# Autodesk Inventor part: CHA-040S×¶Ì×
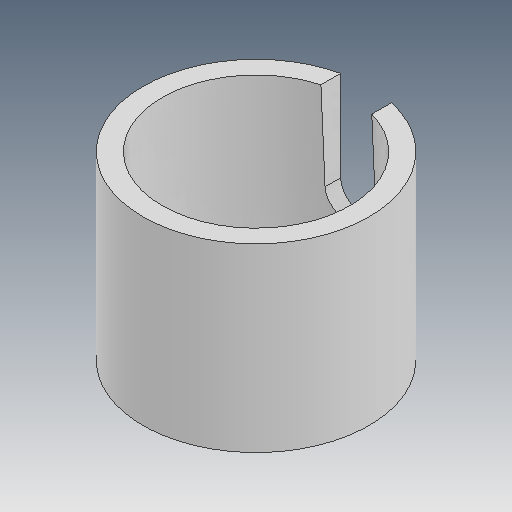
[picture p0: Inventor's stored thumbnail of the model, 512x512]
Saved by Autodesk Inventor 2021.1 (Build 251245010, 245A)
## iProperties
Created: 2019-05
Part Number: CHA-040S×¶Ì×
Material: Ogólny
Document SubType Name: Modeling
Designer: user
Density: 1 g/cm^3
Appearance: Domyślna
Author: user
Revision Number: ÈÎºÎ
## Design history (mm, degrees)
feature "ÊäÈë1"
node "Bryła1"
